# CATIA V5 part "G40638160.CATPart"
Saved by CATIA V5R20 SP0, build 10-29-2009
Part number: G40638160
Revision: 4
Definition: design
Nomenclature: G40638160
Source: made
Description: NOT SPECIFIED
Bounding box of the stored display mesh (mm): x -80 to 80, y -12.5 to 12.5, z -38 to 0
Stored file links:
  C:\Users\Raffaele\Desktop\3D X SITO CF\BOLEX\30-GUIDE STRIP REF 406\G40638160.CATPart
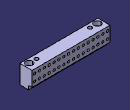
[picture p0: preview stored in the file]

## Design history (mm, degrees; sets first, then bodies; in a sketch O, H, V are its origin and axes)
Body1 "MANIFOLD_SOLID_BREP #5560" (main body)
  Solid1: solid without history
Body2 "MANIFOLD_SOLID_BREP #5698"
  Solid2: solid without history
Body3 "MANIFOLD_SOLID_BREP #5836"
  Solid3: solid without history
Body4 "MANIFOLD_SOLID_BREP #5974"
  Solid4: solid without history
Body5 "MANIFOLD_SOLID_BREP #6112"
  Solid5: solid without history
Body6 "MANIFOLD_SOLID_BREP #6250"
  Solid6: solid without history
Body7 "MANIFOLD_SOLID_BREP #6362"
  Solid7: solid without history
Body8 "MANIFOLD_SOLID_BREP #6474"
  Solid8: solid without history
Body9 "MANIFOLD_SOLID_BREP #6586"
  Solid9: solid without history
Body10 "MANIFOLD_SOLID_BREP #6698"
  Solid10: solid without history
Body11 "MANIFOLD_SOLID_BREP #6810"
  Solid11: solid without history
Body12 "MANIFOLD_SOLID_BREP #6922"
  Solid12: solid without history
Body13 "MANIFOLD_SOLID_BREP #7060"
  Solid13: solid without history
Body14 "MANIFOLD_SOLID_BREP #7198"
  Solid14: solid without history
Body15 "MANIFOLD_SOLID_BREP #7310"
  Solid15: solid without history
Body16 "MANIFOLD_SOLID_BREP #7422"
  Solid16: solid without history
Body17 "MANIFOLD_SOLID_BREP #7534"
  Solid17: solid without history
Body18 "MANIFOLD_SOLID_BREP #7646"
  Solid18: solid without history
Body19 "MANIFOLD_SOLID_BREP #7758"
  Solid19: solid without history
Body20 "MANIFOLD_SOLID_BREP #7870"
  Solid20: solid without history
Body21 "MANIFOLD_SOLID_BREP #7982"
  Solid21: solid without history
Body22 "MANIFOLD_SOLID_BREP #8094"
  Solid22: solid without history
Body23 "MANIFOLD_SOLID_BREP #8206"
  Solid23: solid without history
Body24 "MANIFOLD_SOLID_BREP #8318"
  Solid24: solid without history
Body25 "MANIFOLD_SOLID_BREP #8456"
  Solid25: solid without history
Body26 "MANIFOLD_SOLID_BREP #8594"
  Solid26: solid without history
Body27 "MANIFOLD_SOLID_BREP #8706"
  Solid27: solid without history
Body28 "MANIFOLD_SOLID_BREP #8818"
  Solid28: solid without history
Body29 "MANIFOLD_SOLID_BREP #8930"
  Solid29: solid without history
Body30 "MANIFOLD_SOLID_BREP #9042"
  Solid30: solid without history
Body31 "MANIFOLD_SOLID_BREP #9180"
  Solid31: solid without history
Body32 "MANIFOLD_SOLID_BREP #9318"
  Solid32: solid without history
Body33 "MANIFOLD_SOLID_BREP #9456"
  Solid33: solid without history
Body34 "MANIFOLD_SOLID_BREP #9594"
  Solid34: solid without history
Body35 "MANIFOLD_SOLID_BREP #9732"
  Solid35: solid without history
Body36 "MANIFOLD_SOLID_BREP #9870"
  Solid36: solid without history
Body37 "MANIFOLD_SOLID_BREP #9982"
  Solid37: solid without history
Body38 "MANIFOLD_SOLID_BREP #10094"
  Solid38: solid without history
Body39 "MANIFOLD_SOLID_BREP #10206"
  Solid39: solid without history
Body40 "MANIFOLD_SOLID_BREP #10318"
  Solid40: solid without history
Body41 "MANIFOLD_SOLID_BREP #10430"
  Solid41: solid without history
Body42 "MANIFOLD_SOLID_BREP #10542"
  Solid42: solid without history
Body43 "MANIFOLD_SOLID_BREP #10654"
  Solid43: solid without history
Body44 "MANIFOLD_SOLID_BREP #10766"
  Solid44: solid without history
Body45 "MANIFOLD_SOLID_BREP #10878"
  Solid45: solid without history
Body46 "MANIFOLD_SOLID_BREP #10990"
  Solid46: solid without history
Body47 "MANIFOLD_SOLID_BREP #11102"
  Solid47: solid without history
Body48 "MANIFOLD_SOLID_BREP #11214"
  Solid48: solid without history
